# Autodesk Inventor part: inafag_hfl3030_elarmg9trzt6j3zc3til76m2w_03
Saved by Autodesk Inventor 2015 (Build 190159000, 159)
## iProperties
Company: TraceParts S.A.
Created: 2012-12
Part Number: inafag_hfl3030_elarmg9trzt6j3zc3til76m2w_03
Checked By: TraceParts S.A.
Catalog Web Link: www.traceparts.com
Document SubType Name: Modeling
Designer: TraceParts
Material: Generic
Density: 1 g/cm^3
Appearance: Default
Author: TraceParts
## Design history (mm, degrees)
feature "inafag_hfl3030_elarmg9trzt6j3zc3til76m2w"
body "Solid1"
